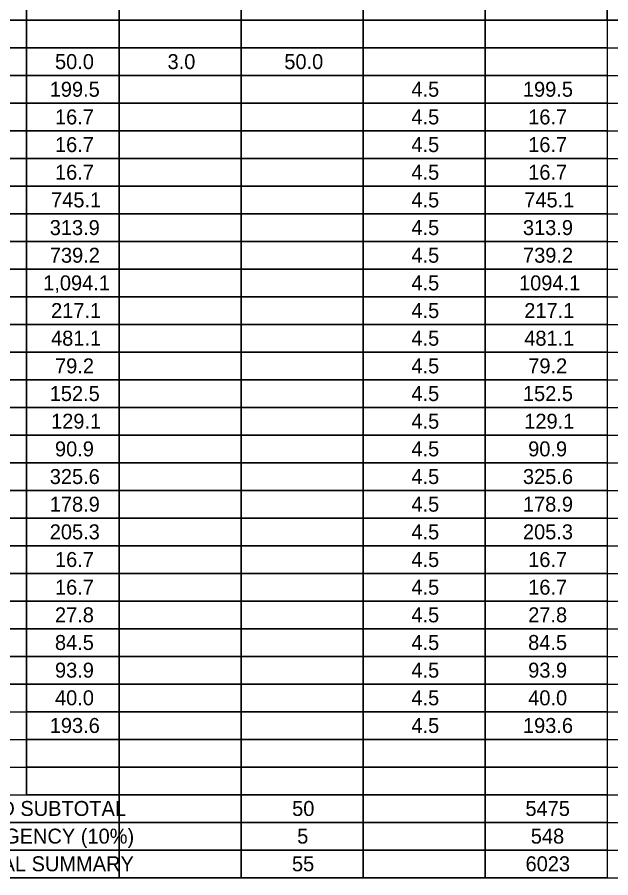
# Model space of a CAD drawing. Extents: x 0 to 34, y 0 to 22.
# Drawn here: x 10.67 to 16.15, y 5.87 to 13.81 of the extents above; entities that cross this region are included whole.
import ezdxf

# ---------------------------------------------------------------- set-up
doc = ezdxf.new("R2010")
doc.units = 0
doc.layers.add('SH_Text', color=7, linetype='Continuous')

msp = doc.modelspace()

# ---------------------------------------------------------------- linework, layer by layer
at = {"layer": 'SH_Text'}
for p, q in [((11.6147, 16.5685), (11.6147, 6.6385)), ((16.1147, 16.5685), (16.1147, 5.8735)), ((10.7597, 16.0735), (10.7597, 6.6385)), ((13.8647, 16.0735), (13.8647, 5.8735)), ((12.7397, 14.7985), (12.7397, 5.8735)), ((14.9897, 14.7985), (14.9897, 5.8735)), ((5.2547, 13.7785), (27.9497, 13.7785)), ((5.2547, 13.5235), (27.9497, 13.5235)), ((5.2547, 13.2685), (27.9497, 13.2685)), ((5.2547, 13.0135), (27.9497, 13.0135)), ((5.2547, 12.7585), (27.9497, 12.7585)), ((5.2547, 12.5035), (27.9497, 12.5035)), ((5.2547, 12.2485), (27.9497, 12.2485)), ((5.2547, 11.9935), (27.9497, 11.9935)), ((5.2547, 11.7385), (27.9497, 11.7385)), ((5.2547, 11.4835), (27.9497, 11.4835)), ((5.2547, 11.2285), (27.9497, 11.2285)), ((5.2547, 10.9735), (27.9497, 10.9735)), ((5.2547, 10.7185), (27.9497, 10.7185)), ((5.2547, 10.4635), (27.9497, 10.4635)), ((5.2547, 10.2085), (27.9497, 10.2085)), ((5.2547, 9.9535), (27.9497, 9.9535)), ((5.2547, 9.6985), (27.9497, 9.6985)), ((5.2547, 9.4435), (27.9497, 9.4435)), ((5.2547, 9.1885), (27.9497, 9.1885)), ((5.2547, 8.9335), (27.9497, 8.9335)), ((5.2547, 8.6785), (27.9497, 8.6785)), ((5.2547, 8.4235), (27.9497, 8.4235)), ((5.2547, 8.1685), (27.9497, 8.1685)), ((5.2547, 7.9135), (27.9497, 7.9135)), ((5.2547, 7.6585), (27.9497, 7.6585)), ((5.2547, 7.4035), (27.9497, 7.4035)), ((5.2547, 7.1485), (27.9497, 7.1485)), ((5.2547, 6.8935), (27.9497, 6.8935)), ((5.2547, 6.6385), (27.9497, 6.6385)), ((11.6147, 6.6385), (11.6147, 5.8735)), ((5.2547, 6.3835), (27.9497, 6.3835)), ((5.2547, 6.1285), (27.9497, 6.1285)), ((5.2547, 5.8735), (27.9497, 5.8735))]:
    msp.add_line(p, q, dxfattribs=at)
for points in [[(16.1147, 16.0735), (27.9497, 16.0735), (27.9497, 13.7785), (16.1147, 13.7785)], [(10.0547, 14.0335), (10.7597, 14.0335), (10.7597, 13.7785), (10.0547, 13.7785)], [(10.7597, 14.0335), (11.6147, 14.0335), (11.6147, 13.7785), (10.7597, 13.7785)], [(11.6147, 14.0335), (12.7397, 14.0335), (12.7397, 13.7785), (11.6147, 13.7785)], [(12.7397, 14.0335), (13.8647, 14.0335), (13.8647, 13.7785), (12.7397, 13.7785)], [(13.8647, 14.0335), (14.9897, 14.0335), (14.9897, 13.7785), (13.8647, 13.7785)], [(14.9897, 14.0335), (16.1147, 14.0335), (16.1147, 13.7785), (14.9897, 13.7785)], [(10.0547, 13.7785), (10.7597, 13.7785), (10.7597, 13.5235), (10.0547, 13.5235)], [(10.7597, 13.7785), (11.6147, 13.7785), (11.6147, 13.5235), (10.7597, 13.5235)], [(11.6147, 13.7785), (12.7397, 13.7785), (12.7397, 13.5235), (11.6147, 13.5235)], [(12.7397, 13.7785), (13.8647, 13.7785), (13.8647, 13.5235), (12.7397, 13.5235)], [(13.8647, 13.7785), (14.9897, 13.7785), (14.9897, 13.5235), (13.8647, 13.5235)], [(14.9897, 13.7785), (16.1147, 13.7785), (16.1147, 13.5235), (14.9897, 13.5235)], [(10.0547, 13.5235), (10.7597, 13.5235), (10.7597, 13.2685), (10.0547, 13.2685)], [(10.7597, 13.5235), (11.6147, 13.5235), (11.6147, 13.2685), (10.7597, 13.2685)], [(11.6147, 13.5235), (12.7397, 13.5235), (12.7397, 13.2685), (11.6147, 13.2685)], [(12.7397, 13.5235), (13.8647, 13.5235), (13.8647, 13.2685), (12.7397, 13.2685)], [(13.8647, 13.5235), (14.9897, 13.5235), (14.9897, 13.2685), (13.8647, 13.2685)], [(14.9897, 13.5235), (16.1147, 13.5235), (16.1147, 13.2685), (14.9897, 13.2685)], [(10.0547, 13.2685), (10.7597, 13.2685), (10.7597, 13.0135), (10.0547, 13.0135)], [(10.7597, 13.2685), (11.6147, 13.2685), (11.6147, 13.0135), (10.7597, 13.0135)], [(11.6147, 13.2685), (12.7397, 13.2685), (12.7397, 13.0135), (11.6147, 13.0135)], [(12.7397, 13.2685), (13.8647, 13.2685), (13.8647, 13.0135), (12.7397, 13.0135)], [(13.8647, 13.2685), (14.9897, 13.2685), (14.9897, 13.0135), (13.8647, 13.0135)], [(14.9897, 13.2685), (16.1147, 13.2685), (16.1147, 13.0135), (14.9897, 13.0135)], [(10.0547, 13.0135), (10.7597, 13.0135), (10.7597, 12.7585), (10.0547, 12.7585)], [(10.7597, 13.0135), (11.6147, 13.0135), (11.6147, 12.7585), (10.7597, 12.7585)], [(11.6147, 13.0135), (12.7397, 13.0135), (12.7397, 12.7585), (11.6147, 12.7585)], [(12.7397, 13.0135), (13.8647, 13.0135), (13.8647, 12.7585), (12.7397, 12.7585)], [(13.8647, 13.0135), (14.9897, 13.0135), (14.9897, 12.7585), (13.8647, 12.7585)], [(14.9897, 13.0135), (16.1147, 13.0135), (16.1147, 12.7585), (14.9897, 12.7585)], [(10.0547, 12.7585), (10.7597, 12.7585), (10.7597, 12.5035), (10.0547, 12.5035)], [(10.7597, 12.7585), (11.6147, 12.7585), (11.6147, 12.5035), (10.7597, 12.5035)], [(11.6147, 12.7585), (12.7397, 12.7585), (12.7397, 12.5035), (11.6147, 12.5035)], [(12.7397, 12.7585), (13.8647, 12.7585), (13.8647, 12.5035), (12.7397, 12.5035)], [(13.8647, 12.7585), (14.9897, 12.7585), (14.9897, 12.5035), (13.8647, 12.5035)], [(14.9897, 12.7585), (16.1147, 12.7585), (16.1147, 12.5035), (14.9897, 12.5035)], [(10.0547, 12.5035), (10.7597, 12.5035), (10.7597, 12.2485), (10.0547, 12.2485)], [(10.7597, 12.5035), (11.6147, 12.5035), (11.6147, 12.2485), (10.7597, 12.2485)], [(11.6147, 12.5035), (12.7397, 12.5035), (12.7397, 12.2485), (11.6147, 12.2485)], [(12.7397, 12.5035), (13.8647, 12.5035), (13.8647, 12.2485), (12.7397, 12.2485)], [(13.8647, 12.5035), (14.9897, 12.5035), (14.9897, 12.2485), (13.8647, 12.2485)], [(14.9897, 12.5035), (16.1147, 12.5035), (16.1147, 12.2485), (14.9897, 12.2485)], [(10.0547, 12.2485), (10.7597, 12.2485), (10.7597, 11.9935), (10.0547, 11.9935)], [(10.7597, 12.2485), (11.6147, 12.2485), (11.6147, 11.9935), (10.7597, 11.9935)], [(11.6147, 12.2485), (12.7397, 12.2485), (12.7397, 11.9935), (11.6147, 11.9935)], [(12.7397, 12.2485), (13.8647, 12.2485), (13.8647, 11.9935), (12.7397, 11.9935)], [(13.8647, 12.2485), (14.9897, 12.2485), (14.9897, 11.9935), (13.8647, 11.9935)], [(14.9897, 12.2485), (16.1147, 12.2485), (16.1147, 11.9935), (14.9897, 11.9935)], [(10.0547, 11.9935), (10.7597, 11.9935), (10.7597, 11.7385), (10.0547, 11.7385)], [(10.7597, 11.9935), (11.6147, 11.9935), (11.6147, 11.7385), (10.7597, 11.7385)], [(11.6147, 11.9935), (12.7397, 11.9935), (12.7397, 11.7385), (11.6147, 11.7385)], [(12.7397, 11.9935), (13.8647, 11.9935), (13.8647, 11.7385), (12.7397, 11.7385)], [(13.8647, 11.9935), (14.9897, 11.9935), (14.9897, 11.7385), (13.8647, 11.7385)], [(14.9897, 11.9935), (16.1147, 11.9935), (16.1147, 11.7385), (14.9897, 11.7385)], [(10.0547, 11.7385), (10.7597, 11.7385), (10.7597, 11.4835), (10.0547, 11.4835)], [(10.7597, 11.7385), (11.6147, 11.7385), (11.6147, 11.4835), (10.7597, 11.4835)], [(11.6147, 11.7385), (12.7397, 11.7385), (12.7397, 11.4835), (11.6147, 11.4835)], [(12.7397, 11.7385), (13.8647, 11.7385), (13.8647, 11.4835), (12.7397, 11.4835)], [(13.8647, 11.7385), (14.9897, 11.7385), (14.9897, 11.4835), (13.8647, 11.4835)], [(14.9897, 11.7385), (16.1147, 11.7385), (16.1147, 11.4835), (14.9897, 11.4835)], [(10.0547, 11.4835), (10.7597, 11.4835), (10.7597, 11.2285), (10.0547, 11.2285)], [(10.7597, 11.4835), (11.6147, 11.4835), (11.6147, 11.2285), (10.7597, 11.2285)], [(11.6147, 11.4835), (12.7397, 11.4835), (12.7397, 11.2285), (11.6147, 11.2285)], [(12.7397, 11.4835), (13.8647, 11.4835), (13.8647, 11.2285), (12.7397, 11.2285)], [(13.8647, 11.4835), (14.9897, 11.4835), (14.9897, 11.2285), (13.8647, 11.2285)], [(14.9897, 11.4835), (16.1147, 11.4835), (16.1147, 11.2285), (14.9897, 11.2285)], [(10.0547, 11.2285), (10.7597, 11.2285), (10.7597, 10.9735), (10.0547, 10.9735)], [(10.7597, 11.2285), (11.6147, 11.2285), (11.6147, 10.9735), (10.7597, 10.9735)], [(11.6147, 11.2285), (12.7397, 11.2285), (12.7397, 10.9735), (11.6147, 10.9735)], [(12.7397, 11.2285), (13.8647, 11.2285), (13.8647, 10.9735), (12.7397, 10.9735)], [(13.8647, 11.2285), (14.9897, 11.2285), (14.9897, 10.9735), (13.8647, 10.9735)], [(14.9897, 11.2285), (16.1147, 11.2285), (16.1147, 10.9735), (14.9897, 10.9735)], [(10.0547, 10.9735), (10.7597, 10.9735), (10.7597, 10.7185), (10.0547, 10.7185)], [(10.7597, 10.9735), (11.6147, 10.9735), (11.6147, 10.7185), (10.7597, 10.7185)], [(11.6147, 10.9735), (12.7397, 10.9735), (12.7397, 10.7185), (11.6147, 10.7185)], [(12.7397, 10.9735), (13.8647, 10.9735), (13.8647, 10.7185), (12.7397, 10.7185)], [(13.8647, 10.9735), (14.9897, 10.9735), (14.9897, 10.7185), (13.8647, 10.7185)], [(14.9897, 10.9735), (16.1147, 10.9735), (16.1147, 10.7185), (14.9897, 10.7185)], [(10.0547, 10.7185), (10.7597, 10.7185), (10.7597, 10.4635), (10.0547, 10.4635)], [(10.7597, 10.7185), (11.6147, 10.7185), (11.6147, 10.4635), (10.7597, 10.4635)], [(11.6147, 10.7185), (12.7397, 10.7185), (12.7397, 10.4635), (11.6147, 10.4635)], [(12.7397, 10.7185), (13.8647, 10.7185), (13.8647, 10.4635), (12.7397, 10.4635)], [(13.8647, 10.7185), (14.9897, 10.7185), (14.9897, 10.4635), (13.8647, 10.4635)], [(14.9897, 10.7185), (16.1147, 10.7185), (16.1147, 10.4635), (14.9897, 10.4635)], [(10.0547, 10.4635), (10.7597, 10.4635), (10.7597, 10.2085), (10.0547, 10.2085)], [(10.7597, 10.4635), (11.6147, 10.4635), (11.6147, 10.2085), (10.7597, 10.2085)], [(11.6147, 10.4635), (12.7397, 10.4635), (12.7397, 10.2085), (11.6147, 10.2085)], [(12.7397, 10.4635), (13.8647, 10.4635), (13.8647, 10.2085), (12.7397, 10.2085)], [(13.8647, 10.4635), (14.9897, 10.4635), (14.9897, 10.2085), (13.8647, 10.2085)], [(14.9897, 10.4635), (16.1147, 10.4635), (16.1147, 10.2085), (14.9897, 10.2085)], [(10.0547, 10.2085), (10.7597, 10.2085), (10.7597, 9.9535), (10.0547, 9.9535)], [(10.7597, 10.2085), (11.6147, 10.2085), (11.6147, 9.9535), (10.7597, 9.9535)], [(11.6147, 10.2085), (12.7397, 10.2085), (12.7397, 9.9535), (11.6147, 9.9535)], [(12.7397, 10.2085), (13.8647, 10.2085), (13.8647, 9.9535), (12.7397, 9.9535)], [(13.8647, 10.2085), (14.9897, 10.2085), (14.9897, 9.9535), (13.8647, 9.9535)], [(14.9897, 10.2085), (16.1147, 10.2085), (16.1147, 9.9535), (14.9897, 9.9535)], [(10.0547, 9.9535), (10.7597, 9.9535), (10.7597, 9.6985), (10.0547, 9.6985)], [(10.7597, 9.9535), (11.6147, 9.9535), (11.6147, 9.6985), (10.7597, 9.6985)], [(11.6147, 9.9535), (12.7397, 9.9535), (12.7397, 9.6985), (11.6147, 9.6985)], [(12.7397, 9.9535), (13.8647, 9.9535), (13.8647, 9.6985), (12.7397, 9.6985)], [(13.8647, 9.9535), (14.9897, 9.9535), (14.9897, 9.6985), (13.8647, 9.6985)], [(14.9897, 9.9535), (16.1147, 9.9535), (16.1147, 9.6985), (14.9897, 9.6985)], [(10.0547, 9.6985), (10.7597, 9.6985), (10.7597, 9.4435), (10.0547, 9.4435)], [(10.7597, 9.6985), (11.6147, 9.6985), (11.6147, 9.4435), (10.7597, 9.4435)], [(11.6147, 9.6985), (12.7397, 9.6985), (12.7397, 9.4435), (11.6147, 9.4435)], [(12.7397, 9.6985), (13.8647, 9.6985), (13.8647, 9.4435), (12.7397, 9.4435)], [(13.8647, 9.6985), (14.9897, 9.6985), (14.9897, 9.4435), (13.8647, 9.4435)], [(14.9897, 9.6985), (16.1147, 9.6985), (16.1147, 9.4435), (14.9897, 9.4435)], [(10.0547, 9.4435), (10.7597, 9.4435), (10.7597, 9.1885), (10.0547, 9.1885)], [(10.7597, 9.4435), (11.6147, 9.4435), (11.6147, 9.1885), (10.7597, 9.1885)], [(11.6147, 9.4435), (12.7397, 9.4435), (12.7397, 9.1885), (11.6147, 9.1885)], [(12.7397, 9.4435), (13.8647, 9.4435), (13.8647, 9.1885), (12.7397, 9.1885)], [(13.8647, 9.4435), (14.9897, 9.4435), (14.9897, 9.1885), (13.8647, 9.1885)], [(14.9897, 9.4435), (16.1147, 9.4435), (16.1147, 9.1885), (14.9897, 9.1885)], [(10.0547, 9.1885), (10.7597, 9.1885), (10.7597, 8.9335), (10.0547, 8.9335)], [(10.7597, 9.1885), (11.6147, 9.1885), (11.6147, 8.9335), (10.7597, 8.9335)], [(11.6147, 9.1885), (12.7397, 9.1885), (12.7397, 8.9335), (11.6147, 8.9335)], [(12.7397, 9.1885), (13.8647, 9.1885), (13.8647, 8.9335), (12.7397, 8.9335)], [(13.8647, 9.1885), (14.9897, 9.1885), (14.9897, 8.9335), (13.8647, 8.9335)], [(14.9897, 9.1885), (16.1147, 9.1885), (16.1147, 8.9335), (14.9897, 8.9335)], [(10.0547, 8.9335), (10.7597, 8.9335), (10.7597, 8.6785), (10.0547, 8.6785)], [(10.7597, 8.9335), (11.6147, 8.9335), (11.6147, 8.6785), (10.7597, 8.6785)], [(11.6147, 8.9335), (12.7397, 8.9335), (12.7397, 8.6785), (11.6147, 8.6785)], [(12.7397, 8.9335), (13.8647, 8.9335), (13.8647, 8.6785), (12.7397, 8.6785)], [(13.8647, 8.9335), (14.9897, 8.9335), (14.9897, 8.6785), (13.8647, 8.6785)], [(14.9897, 8.9335), (16.1147, 8.9335), (16.1147, 8.6785), (14.9897, 8.6785)], [(10.0547, 8.6785), (10.7597, 8.6785), (10.7597, 8.4235), (10.0547, 8.4235)], [(10.7597, 8.6785), (11.6147, 8.6785), (11.6147, 8.4235), (10.7597, 8.4235)], [(11.6147, 8.6785), (12.7397, 8.6785), (12.7397, 8.4235), (11.6147, 8.4235)], [(12.7397, 8.6785), (13.8647, 8.6785), (13.8647, 8.4235), (12.7397, 8.4235)], [(13.8647, 8.6785), (14.9897, 8.6785), (14.9897, 8.4235), (13.8647, 8.4235)], [(14.9897, 8.6785), (16.1147, 8.6785), (16.1147, 8.4235), (14.9897, 8.4235)], [(10.0547, 8.4235), (10.7597, 8.4235), (10.7597, 8.1685), (10.0547, 8.1685)], [(10.7597, 8.4235), (11.6147, 8.4235), (11.6147, 8.1685), (10.7597, 8.1685)], [(11.6147, 8.4235), (12.7397, 8.4235), (12.7397, 8.1685), (11.6147, 8.1685)], [(12.7397, 8.4235), (13.8647, 8.4235), (13.8647, 8.1685), (12.7397, 8.1685)], [(13.8647, 8.4235), (14.9897, 8.4235), (14.9897, 8.1685), (13.8647, 8.1685)], [(14.9897, 8.4235), (16.1147, 8.4235), (16.1147, 8.1685), (14.9897, 8.1685)], [(10.0547, 8.1685), (10.7597, 8.1685), (10.7597, 7.9135), (10.0547, 7.9135)], [(10.7597, 8.1685), (11.6147, 8.1685), (11.6147, 7.9135), (10.7597, 7.9135)], [(11.6147, 8.1685), (12.7397, 8.1685), (12.7397, 7.9135), (11.6147, 7.9135)], [(12.7397, 8.1685), (13.8647, 8.1685), (13.8647, 7.9135), (12.7397, 7.9135)], [(13.8647, 8.1685), (14.9897, 8.1685), (14.9897, 7.9135), (13.8647, 7.9135)], [(14.9897, 8.1685), (16.1147, 8.1685), (16.1147, 7.9135), (14.9897, 7.9135)], [(10.0547, 7.9135), (10.7597, 7.9135), (10.7597, 7.6585), (10.0547, 7.6585)], [(10.7597, 7.9135), (11.6147, 7.9135), (11.6147, 7.6585), (10.7597, 7.6585)], [(11.6147, 7.9135), (12.7397, 7.9135), (12.7397, 7.6585), (11.6147, 7.6585)], [(12.7397, 7.9135), (13.8647, 7.9135), (13.8647, 7.6585), (12.7397, 7.6585)], [(13.8647, 7.9135), (14.9897, 7.9135), (14.9897, 7.6585), (13.8647, 7.6585)], [(14.9897, 7.9135), (16.1147, 7.9135), (16.1147, 7.6585), (14.9897, 7.6585)], [(10.7597, 7.6585), (11.6147, 7.6585), (11.6147, 7.4035), (10.7597, 7.4035)], [(11.6147, 7.6585), (12.7397, 7.6585), (12.7397, 7.4035), (11.6147, 7.4035)], [(12.7397, 7.6585), (13.8647, 7.6585), (13.8647, 7.4035), (12.7397, 7.4035)], [(13.8647, 7.6585), (14.9897, 7.6585), (14.9897, 7.4035), (13.8647, 7.4035)], [(14.9897, 7.6585), (16.1147, 7.6585), (16.1147, 7.4035), (14.9897, 7.4035)], [(10.7597, 7.4035), (11.6147, 7.4035), (11.6147, 7.1485), (10.7597, 7.1485)], [(11.6147, 7.4035), (12.7397, 7.4035), (12.7397, 7.1485), (11.6147, 7.1485)], [(12.7397, 7.4035), (13.8647, 7.4035), (13.8647, 7.1485), (12.7397, 7.1485)], [(13.8647, 7.4035), (14.9897, 7.4035), (14.9897, 7.1485), (13.8647, 7.1485)], [(14.9897, 7.4035), (16.1147, 7.4035), (16.1147, 7.1485), (14.9897, 7.1485)], [(10.7597, 7.1485), (11.6147, 7.1485), (11.6147, 6.8935), (10.7597, 6.8935)], [(11.6147, 7.1485), (12.7397, 7.1485), (12.7397, 6.8935), (11.6147, 6.8935)], [(12.7397, 7.1485), (13.8647, 7.1485), (13.8647, 6.8935), (12.7397, 6.8935)], [(13.8647, 7.1485), (14.9897, 7.1485), (14.9897, 6.8935), (13.8647, 6.8935)], [(14.9897, 7.1485), (16.1147, 7.1485), (16.1147, 6.8935), (14.9897, 6.8935)], [(10.7597, 6.8935), (11.6147, 6.8935), (11.6147, 6.6385), (10.7597, 6.6385)], [(11.6147, 6.8935), (12.7397, 6.8935), (12.7397, 6.6385), (11.6147, 6.6385)], [(12.7397, 6.8935), (13.8647, 6.8935), (13.8647, 6.6385), (12.7397, 6.6385)], [(13.8647, 6.8935), (14.9897, 6.8935), (14.9897, 6.6385), (13.8647, 6.6385)], [(14.9897, 6.8935), (16.1147, 6.8935), (16.1147, 6.6385), (14.9897, 6.6385)], [(5.2547, 6.6385), (11.6147, 6.6385), (11.6147, 6.3835), (5.2547, 6.3835)], [(11.6147, 6.6385), (12.7397, 6.6385), (12.7397, 6.3835), (11.6147, 6.3835)], [(12.7397, 6.6385), (13.8647, 6.6385), (13.8647, 6.3835), (12.7397, 6.3835)], [(13.8647, 6.6385), (14.9897, 6.6385), (14.9897, 6.3835), (13.8647, 6.3835)], [(14.9897, 6.6385), (16.1147, 6.6385), (16.1147, 6.3835), (14.9897, 6.3835)], [(5.2547, 6.3835), (11.6147, 6.3835), (11.6147, 6.1285), (5.2547, 6.1285)], [(11.6147, 6.3835), (12.7397, 6.3835), (12.7397, 6.1285), (11.6147, 6.1285)], [(12.7397, 6.3835), (13.8647, 6.3835), (13.8647, 6.1285), (12.7397, 6.1285)], [(13.8647, 6.3835), (14.9897, 6.3835), (14.9897, 6.1285), (13.8647, 6.1285)], [(14.9897, 6.3835), (16.1147, 6.3835), (16.1147, 6.1285), (14.9897, 6.1285)], [(5.2547, 6.1285), (11.6147, 6.1285), (11.6147, 5.8735), (5.2547, 5.8735)], [(11.6147, 6.1285), (12.7397, 6.1285), (12.7397, 5.8735), (11.6147, 5.8735)], [(12.7397, 6.1285), (13.8647, 6.1285), (13.8647, 5.8735), (12.7397, 5.8735)], [(13.8647, 6.1285), (14.9897, 6.1285), (14.9897, 5.8735), (13.8647, 5.8735)], [(14.9897, 6.1285), (16.1147, 6.1285), (16.1147, 5.8735), (14.9897, 5.8735)]]:
    msp.add_lwpolyline(points, close=True, dxfattribs=at)

# ---------------------------------------------------------------- texts
for s, p in [('50.0', (11.0226, 13.3285)), ('3.0', (12.0608, 13.3285)), ('50.0', (13.1376, 13.3285)), ('199.5', (10.9737, 13.0735)), ('4.5', (14.3101, 13.0735)), ('199.5', (15.3387, 13.0735)), ('16.7', (11.0224, 12.8185)), ('4.5', (14.3101, 12.8185)), ('16.7', (15.3874, 12.8185)), ('16.7', (11.0224, 12.5635)), ('4.5', (14.3101, 12.5635)), ('16.7', (15.3874, 12.5635)), ('16.7', (11.0224, 12.3085)), ('4.5', (14.3101, 12.3085)), ('16.7', (15.3874, 12.3085)), ('745.1', (10.9862, 12.0535)), ('4.5', (14.3101, 12.0535)), ('745.1', (15.3512, 12.0535)), ('313.9', (10.974, 11.7985)), ('4.5', (14.3101, 11.7985)), ('313.9', (15.339, 11.7985)), ('739.2', (10.9748, 11.5435)), ('4.5', (14.3101, 11.5435)), ('739.2', (15.3398, 11.5435)), ('1,094.1', (10.9138, 11.2885)), ('4.5', (14.3101, 11.2885)), ('1094.1', (15.3029, 11.2885)), ('217.1', (10.9862, 11.0335)), ('4.5', (14.3101, 11.0335)), ('217.1', (15.3512, 11.0335)), ('481.1', (10.9862, 10.7785)), ('4.5', (14.3101, 10.7785)), ('481.1', (15.3512, 10.7785)), ('79.2', (11.023, 10.5235)), ('4.5', (14.3101, 10.5235)), ('79.2', (15.388, 10.5235)), ('152.5', (10.9737, 10.2685)), ('4.5', (14.3101, 10.2685)), ('152.5', (15.3387, 10.2685)), ('129.1', (10.9862, 10.0135)), ('4.5', (14.3101, 10.0135)), ('129.1', (15.3512, 10.0135)), ('90.9', (11.0223, 9.7585)), ('4.5', (14.3101, 9.7585)), ('90.9', (15.3873, 9.7585)), ('325.6', (10.9741, 9.5035)), ('4.5', (14.3101, 9.5035)), ('325.6', (15.3391, 9.5035)), ('178.9', (10.974, 9.2485)), ('4.5', (14.3101, 9.2485)), ('178.9', (15.339, 9.2485)), ('205.3', (10.9741, 8.9935)), ('4.5', (14.3101, 8.9935)), ('205.3', (15.3391, 8.9935)), ('16.7', (11.0224, 8.7385)), ('4.5', (14.3101, 8.7385)), ('16.7', (15.3874, 8.7385)), ('16.7', (11.0224, 8.4835)), ('4.5', (14.3101, 8.4835)), ('16.7', (15.3874, 8.4835)), ('27.8', (11.0223, 8.2285)), ('4.5', (14.3101, 8.2285)), ('27.8', (15.3873, 8.2285)), ('84.5', (11.0219, 7.9735)), ('4.5', (14.3101, 7.9735)), ('84.5', (15.3869, 7.9735)), ('93.9', (11.0223, 7.7185)), ('4.5', (14.3101, 7.7185)), ('93.9', (15.3873, 7.7185)), ('40.0', (11.0226, 7.4635)), ('4.5', (14.3101, 7.4635)), ('40.0', (15.3876, 7.4635)), ('193.6', (10.9741, 7.2085)), ('4.5', (14.3101, 7.2085)), ('193.6', (15.3391, 7.2085)), ('NORTHBOUND SUBTOTAL', (9.3295, 6.4435)), ('50', (13.21, 6.4435)), ('5475', (15.3619, 6.4435)), ('NORTHBOUND CONTINGENCY (10%)', (8.472, 6.1885)), ('5', (13.2566, 6.1885)), ('548', (15.4114, 6.1885)), ('TOTAL CARRIED TO GENERAL SUMMARY', (8.0382, 5.9335)), ('55', (13.2084, 5.9335)), ('6023', (15.363, 5.9335))]:
    msp.add_text(s, height=0.138, dxfattribs=at).set_placement(p)

doc.saveas('drawing.dxf')
